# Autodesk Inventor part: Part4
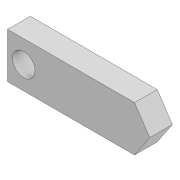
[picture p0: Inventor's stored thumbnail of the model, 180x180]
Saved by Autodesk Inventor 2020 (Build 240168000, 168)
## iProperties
Created: 2019-12
Part Number: Part4
Material: Generic
Document SubType Name: Modeling
Designer: Dell
Density: 1 g/cm^3
Appearance: Default
Author: Dell
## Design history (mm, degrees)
sketch "Sketch1"
  geometry: L1 (0, 0)-(0, 10); L2 (0, 10)-(28, 10); L3 (28, 10)-(31.351, 5); L4 (31.351, 5)-(28, 0); L5 (28, 0)-(0, 0)
  constraints: 10 end point, 2 horizontal, 1 vertical
  dimensions: "d0" = 10 distance of L1.start L1.end; "d1" = 28 distance of L1.end L2.end
extrude "Extrusion1" new body sketch "Sketch1" distance "d2" = 5; taper "d3" = 0 deg
sketch "Sketch2"
  geometry: C1 r 2.5 at (3.567, 5.061); 1 further point
  constraints: 1 centre point
  dimensions: "d4" = 5 diameter of C1
extrude "Extrusion2" cut sketch "Sketch2" distance "d5" = 5; taper "d6" = 0 deg
body "Solid1"
